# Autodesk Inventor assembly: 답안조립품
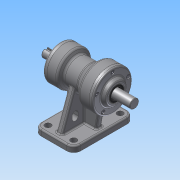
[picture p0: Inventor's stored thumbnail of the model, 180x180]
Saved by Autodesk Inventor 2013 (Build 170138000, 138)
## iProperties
Created: 2015-08
Part Number: 답안조립품
Document SubType Name: Assembly
Designer: Administrator
Author: Administrator
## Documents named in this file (10)
- C:\Users\Administrator\Desktop\450806V1010\답안조립품.iam
- C:\Users\Administrator\Desktop\450806V1010\본체.ipt
- C:\Users\Administrator\Desktop\450806V1010\베어링 6205.ipt
- C:\Users\Administrator\Desktop\450806V1010\베어링 6203.ipt
- C:\Users\Administrator\Desktop\450806V1010\앞커버.ipt
- C:\Users\Administrator\Desktop\450806V1010\오일실 .ipt
- 오일실 .ipt
- C:\Users\Administrator\Desktop\450806V1010\M4x0.5.ipt
- C:\Users\Administrator\Desktop\450806V1010\뒤커버.ipt
- C:\Users\Administrator\Desktop\450806V1010\축.ipt
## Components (10 placed, 1 different names)
1. M4x0.5:1
2. M4x0.5:2
3. M4x0.5:3
4. M4x0.5:4
5. M4x0.5:5
6. M4x0.5:6
7. M4x0.5:7
8. M4x0.5:8
9. M4x0.5:9
10. M4x0.5:10
